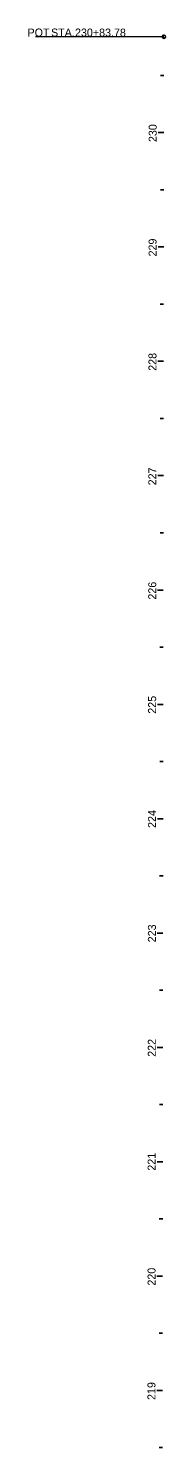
# Model space of a CAD drawing. Extents: x 1805326 to 1810276, y 297762 to 303660.
# Drawn here: x 1808551 to 1808671, y 302419 to 303660 of the extents above; entities that cross this region are included whole.
import ezdxf

# ---------------------------------------------------------------- set-up
doc = ezdxf.new("R2010")
doc.units = 0
doc.layers.add('GE_P_Alignment_100_Cardinal_Points', color=7, linetype='Continuous')
doc.layers.add('GE_P_Alignment_100_Stations', color=7, linetype='Continuous')

msp = doc.modelspace()

# ---------------------------------------------------------------- linework, layer by layer
at = {"layer": 'GE_P_Alignment_100_Cardinal_Points'}
msp.add_line((1808669.4, 303653), (1808556.9, 303653.1), dxfattribs=at)
msp.add_circle((1808669.4, 303653), 1.5, dxfattribs=at)
at = {"layer": 'GE_P_Alignment_100_Stations'}
for p, q in [((1808669.4, 303619.2), (1808666.4, 303619.2)), ((1808669.4, 303569.2), (1808664.4, 303569.2)), ((1808669.3, 303519.2), (1808666.3, 303519.2)), ((1808669.3, 303469.2), (1808664.3, 303469.2)), ((1808669.2, 303419.2), (1808666.2, 303419.2)), ((1808669.2, 303369.2), (1808664.2, 303369.2)), ((1808669.1, 303319.2), (1808666.1, 303319.2)), ((1808669, 303269.2), (1808664, 303269.2)), ((1808669, 303219.2), (1808666, 303219.2)), ((1808668.9, 303169.2), (1808663.9, 303169.2)), ((1808668.9, 303119.2), (1808665.9, 303119.2)), ((1808668.8, 303069.2), (1808663.8, 303069.2)), ((1808668.8, 303019.2), (1808665.8, 303019.2)), ((1808668.7, 302969.2), (1808663.7, 302969.2)), ((1808668.7, 302919.2), (1808665.7, 302919.2)), ((1808668.6, 302869.2), (1808663.6, 302869.2)), ((1808668.6, 302819.2), (1808665.6, 302819.2)), ((1808668.5, 302769.2), (1808663.5, 302769.2)), ((1808668.5, 302719.2), (1808665.5, 302719.2)), ((1808668.4, 302669.2), (1808663.4, 302669.2)), ((1808668.4, 302619.2), (1808665.4, 302619.2)), ((1808668.3, 302569.2), (1808663.3, 302569.2)), ((1808668.3, 302519.2), (1808665.3, 302519.2)), ((1808668.2, 302469.2), (1808663.2, 302469.2)), ((1808668.2, 302419.2), (1808665.2, 302419.2))]:
    msp.add_line(p, q, dxfattribs=at)

# ---------------------------------------------------------------- texts
at = {"layer": 'GE_P_Alignment_100_Cardinal_Points'}
for s, p in [('POT', (1808550, 303653.2)), (' STA. ', (1808568, 303653.2)), ('230+83.78', (1808591.6, 303653.2))]:
    msp.add_text(s, height=7, rotation=359.9418, dxfattribs=at).set_placement(p)
at = {"layer": 'GE_P_Alignment_100_Stations'}
for s, p in [('230', (1808663.1, 303560.9)), ('229', (1808663, 303460.9)), ('228', (1808662.9, 303360.9)), ('227', (1808662.8, 303260.7)), ('226', (1808662.7, 303160.8)), ('225', (1808662.6, 303061)), ('224', (1808662.5, 302961.1)), ('223', (1808662.4, 302861.1)), ('222', (1808662.3, 302761)), ('221', (1808662.2, 302661.4)), ('220', (1808662.1, 302560.9)), ('219', (1808662, 302460.9))]:
    msp.add_text(s, height=7, rotation=89.9418, dxfattribs=at).set_placement(p)

doc.saveas('drawing.dxf')
